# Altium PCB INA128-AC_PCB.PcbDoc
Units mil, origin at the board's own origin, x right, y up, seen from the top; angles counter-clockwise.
Board outline 3000 x 2500 mil, 2 copper layers (Top Layer, Bottom Layer); 43 components, 14 nets, 87 pads, 13 vias.
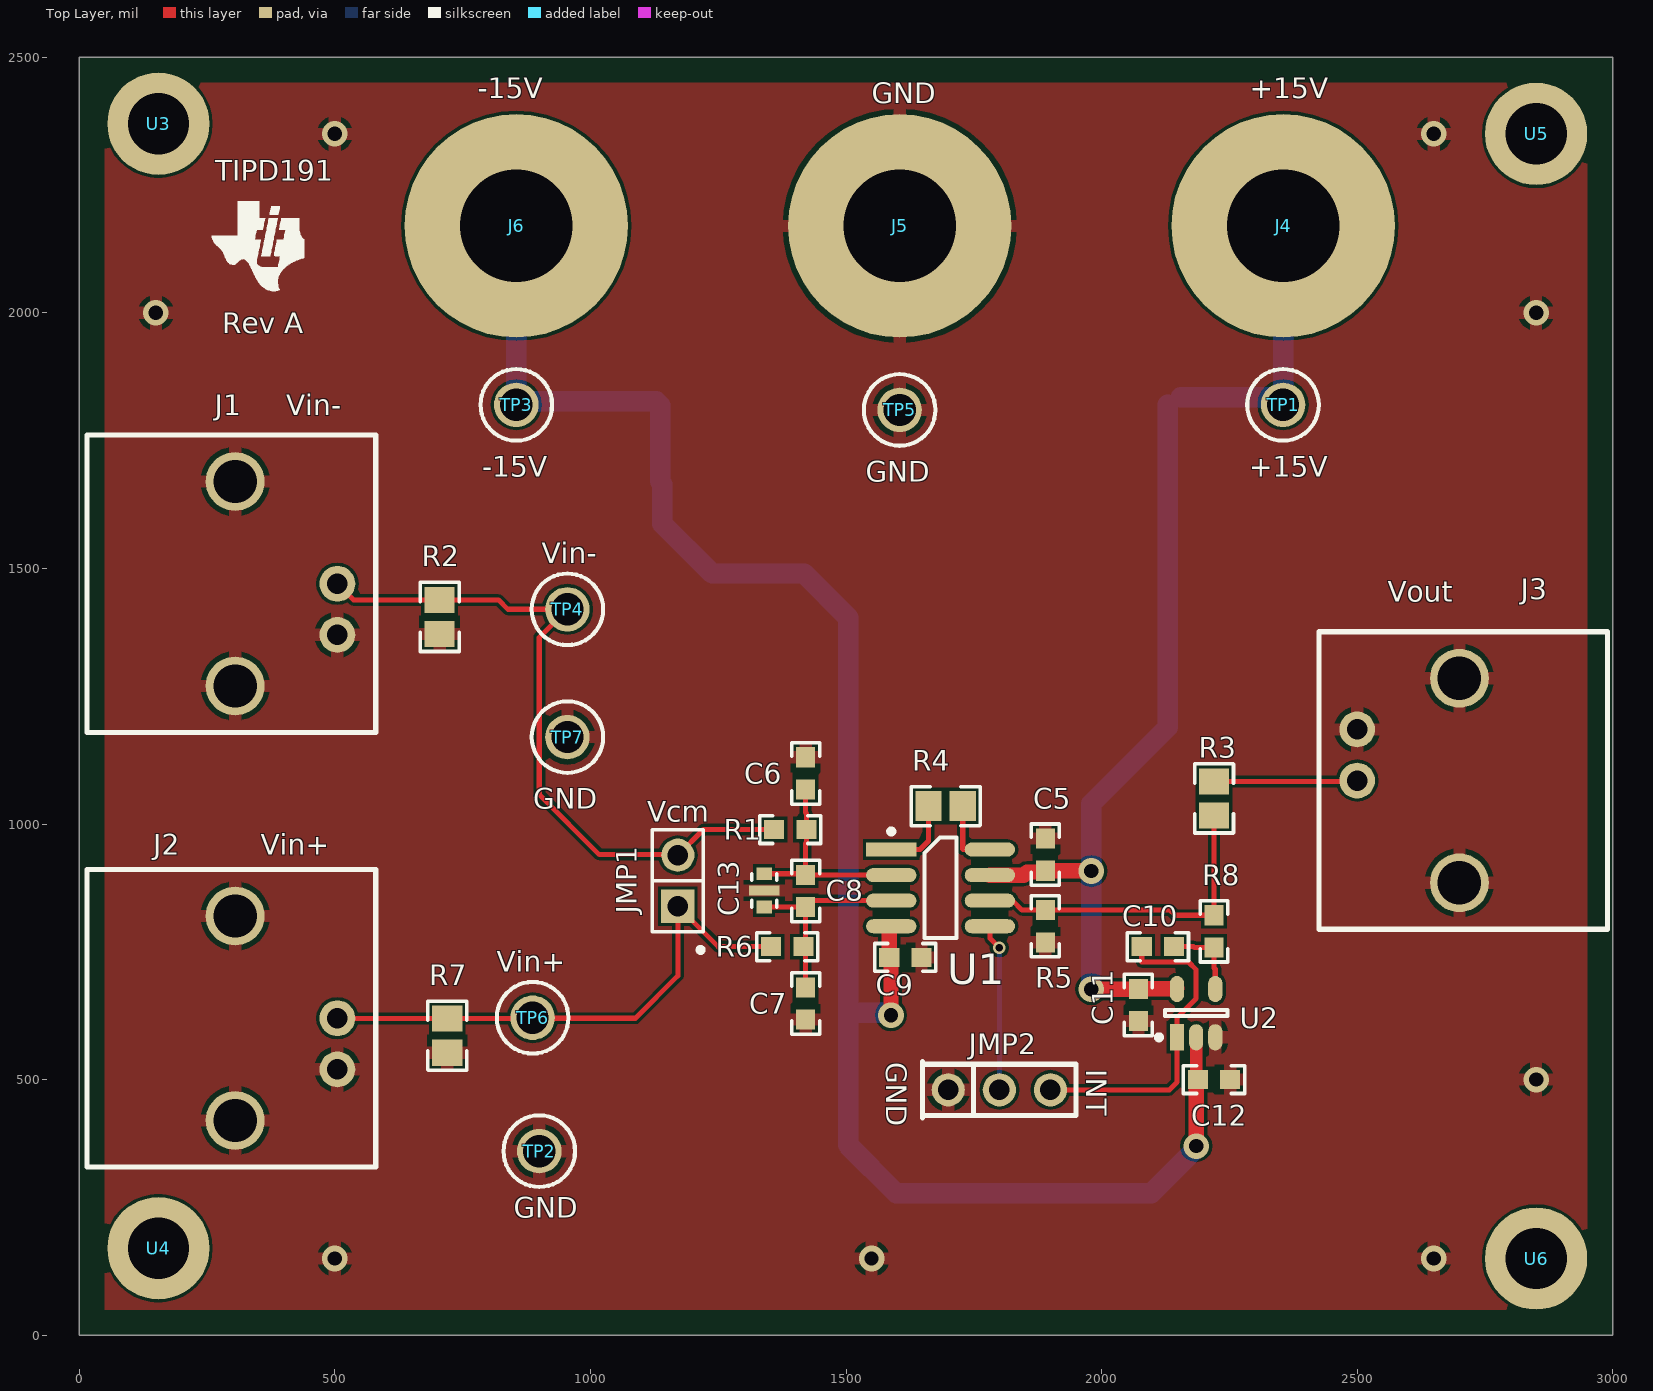
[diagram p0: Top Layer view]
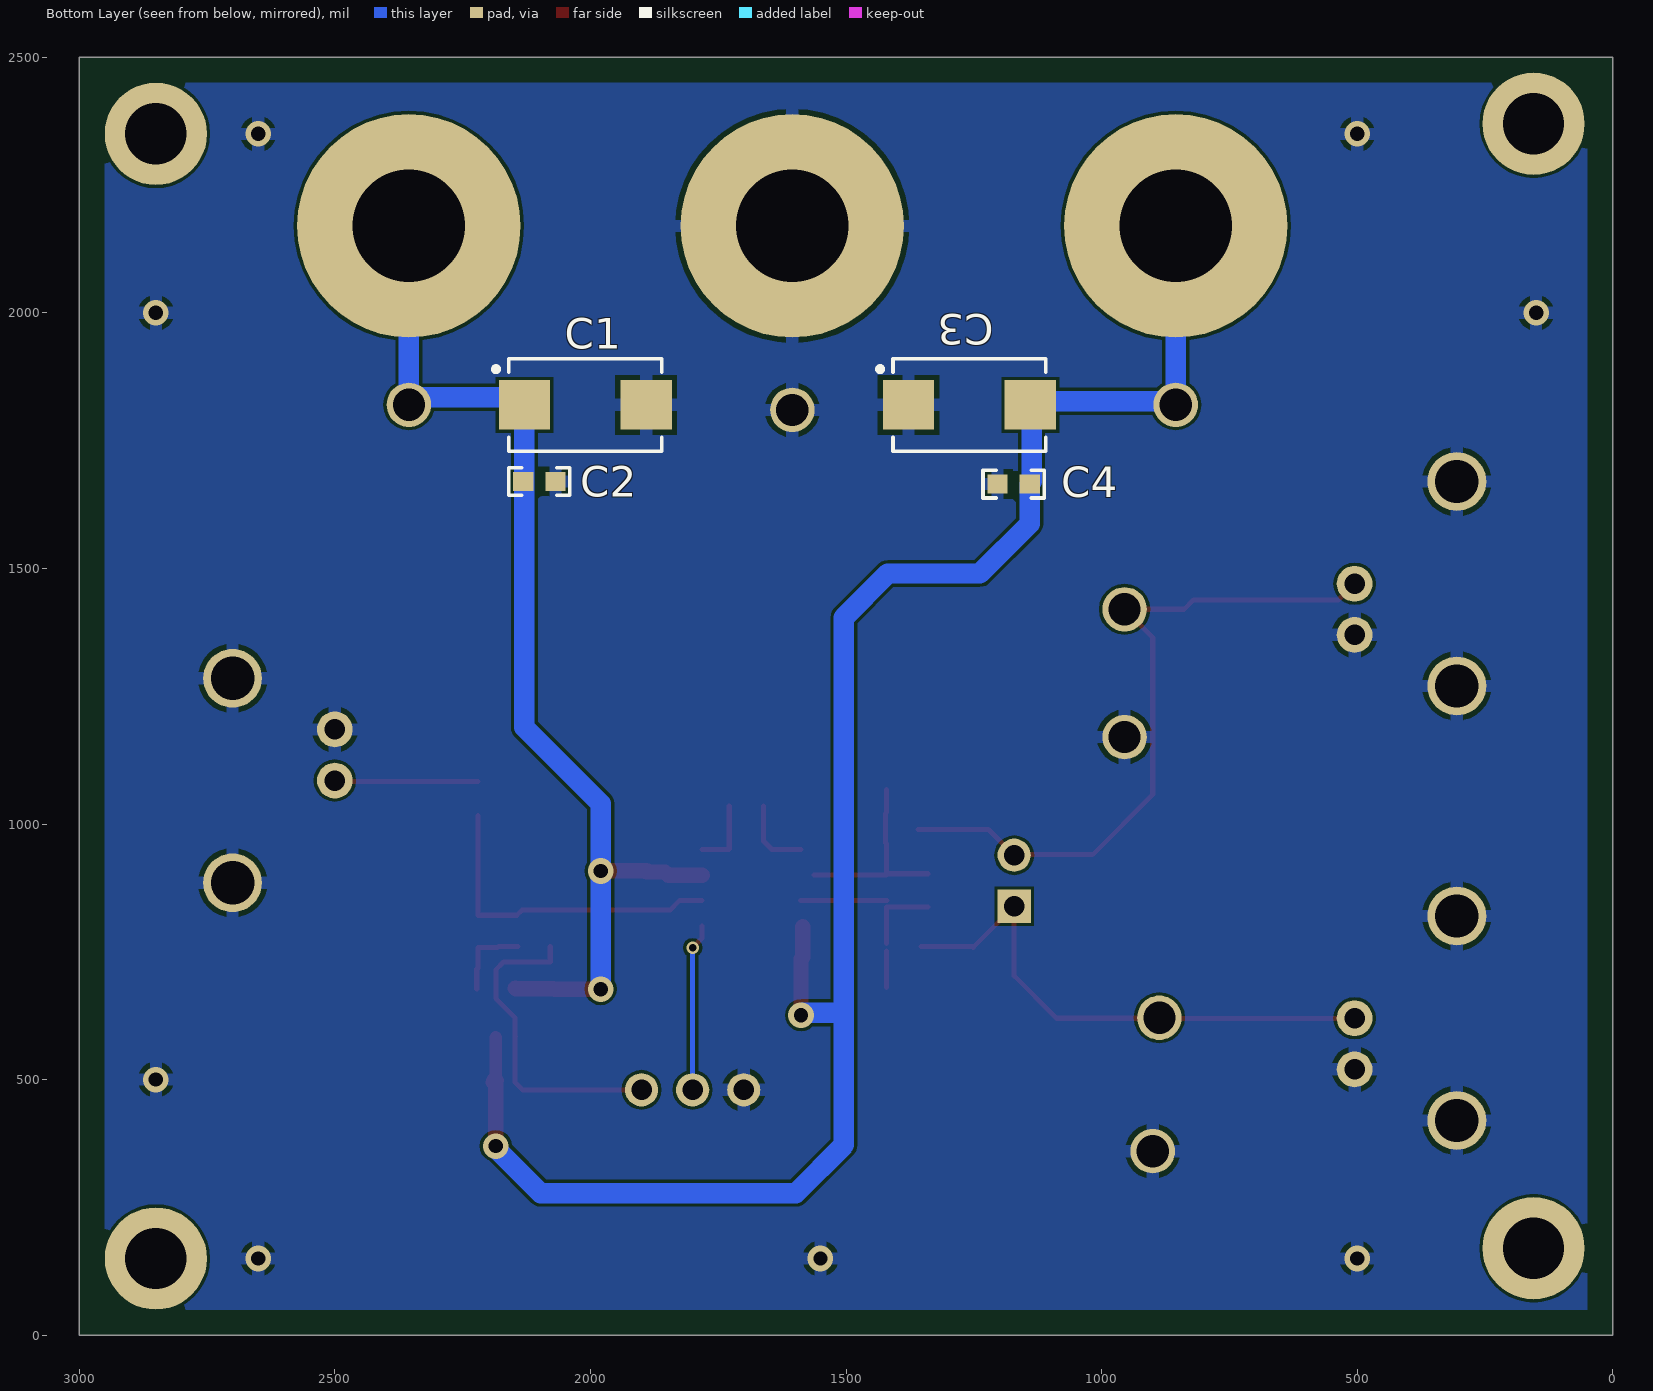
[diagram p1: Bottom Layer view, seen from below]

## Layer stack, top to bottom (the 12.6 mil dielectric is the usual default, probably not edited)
Top Layer: signal copper 1.4
Dielectric: core 12.6, FR-4, Dk 4.8
Bottom Layer: signal copper 1.4

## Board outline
0,2500 0,0 3000,0 3000,2500 0,2500

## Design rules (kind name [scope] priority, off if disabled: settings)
AssemblyTestPointUsage [All] p1 off:
AssemblyTestpoint [All] p1 off: testpointundercomponent=TRUE minsize=40 maxsize=100 preferedsize=60 minholesize=0 maxholesize=40 preferedholesize=32 testpointgrid=1 usegrid=TRUE gridtolerance=0.01 allowsidetop=TRUE allowsidebottom=TRUE
Clearance [All] p1: gap=6
ComponentClearance [All] p1 off: gap=10 collisioncheckmode=3 verticalgap=10 showdistances=FALSE
DiffPairsRouting [All] p1 off: maxlimit=10 minlimit=10 mostfreqgap=10 maxuncoupledlength=500
FabricationTestPointUsage TestPointUsage [All] p1 off: valid=0 allowmultiple=FALSE
FabricationTestpoint Testpoint [All] p1 off: side=3 testpointundercomponent=TRUE minsize=40 maxsize=100 preferedsize=60 minholesize=0 maxholesize=40 preferedholesize=32 testpointgrid=1 allowsidetop=TRUE allowsidebottom=TRUE usegrid=TRUE gridtolerance=0.01
FanoutControl Fanout_BGA [IsBGA] p1 off: bgadir=Out bgaviamode=Centered fanoutstyle=Auto fanoutdirection=Alternating viagrid=1 // Fanout_BGA (Default Rule)
FanoutControl Fanout_LCC [IsLCC] p2 off: bgadir=Out bgaviamode=Centered fanoutstyle=Auto fanoutdirection=Alternating viagrid=1 // Fanout_LCC (Default Rule)
FanoutControl Fanout_SOIC [IsSOIC] p3 off: bgadir=Out bgaviamode=Centered fanoutstyle=Auto fanoutdirection=Alternating viagrid=1 // Fanout_SOIC (Default Rule)
FanoutControl Fanout_Small [(CompPinCount < 5)] p4 off: bgadir=Out bgaviamode=Centered fanoutstyle=Auto fanoutdirection=OutThenIn viagrid=1 // Fanout_Small (Default Rule)
FanoutControl Fanout_Default [All] p5 off: bgadir=Out bgaviamode=Centered fanoutstyle=Auto fanoutdirection=Alternating viagrid=1 // Fanout_Default (Default Rule)
Height [All] p1 off: minheight=0 maxheight=1000 prefheight=500
HoleSize [All] p1: absolutevalues=TRUE maxlimit=400 minlimit=15 maxpercent=80.000 minpercent=20.000
HoleToHoleClearance [All] p1: gap=8 allowstackedmicrovias=TRUE
LayerPairs [All] p1 off: enforce=FALSE
MinimumSolderMaskSliver [All] p1: minsoldermaskwidth=4
PolygonConnect PolygonConnect_1 [InPadClass('GNDVia')] p1: connectstyle=Direct reliefconductorwidth=10 reliefentries=4 polygonreliefangle="90 Angle" airgapwidth=10
PolygonConnect [All] p2: connectstyle=Relief reliefconductorwidth=25 reliefentries=4 polygonreliefangle="90 Angle" airgapwidth=10
RoutingVias [All] p1: holewidth=15 width=25 viastyle="Through Hole" minholewidth=15 minwidth=25 maxholewidth=400 maxwidth=500
SilkToSilkClearance [All] p1: silktosilkclearance=5
SilkscreenOverComponentPads [IsPad] p1: minsilkscreentomaskgap=5
SolderMaskExpansion [All] p1: expansion=2
Width Width_1 [InNetClass('Power')] p1: maxlimit=100 minlimit=10 preferedwidth=30 minimp=50.000000 maximp=50.000000 favimp=50.000000
Width [All] p2: maxlimit=100 minlimit=6 preferedwidth=10
10 further rules are at their usual default settings.

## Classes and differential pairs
net class Power: +15V -15V

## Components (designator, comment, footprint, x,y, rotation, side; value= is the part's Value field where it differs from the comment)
C1 "293D106X9050E2TE3" 7343-43 2010,1820 r180 bottom
C2 "06033D104KAT2A" 0603 2100,1670 r180 bottom
C3 "293D106X9050E2TE3" 7343-43 1258.5,1820 r180 bottom
C4 "06033D104KAT2A" 0603 1172,1665 r180 bottom
C5 "06033D104KAT2A" 0603 1890,940 r90 top
C6 "06031C102JAT2A" 0603 1421,1099 r270 top
C7 "06031C102JAT2A" 0603 1421,649 r270 top
C8 "06031C103JAT2A" 0603 1421,869 r270 top
C9 "06033D104KAT2A" 0603 1616,739 r0 top
C10 "06033D104KAT2A" 0603 2110,760 r180 top
C11 "06033D104KAT2A" 0603 2072,646 r90 top
C12 "06033D104KAT2A" 0603 2220,500 r180 top
C13 "500X14W103MV4T" X2Y_0603 1340,870 r90 top
J1 "Vin-" "Right Angle BNC" 505,1470 r90 top
J2 "Vin+" "Right Angle BNC" 505,620 r90 top
J3 "Vout" "Right Angle BNC" 2500,1085 r270 top
J4 "+15V" "JACK NON-INSULATED .218\"" 2355,2170 r90 top
J5 "GND" "JACK NON-INSULATED .218\"" 1605,2170 r90 top
J6 "-15V" "JACK NON-INSULATED .218\"" 855,2170 r90 top
JMP1 "Vcm" "Header 100mil, 1x2" 1171,889 r90 top
JMP2 "GND" JUMP3 1700,480 r0 top
R1 "CPF0603B100KE" 0603 1391,989 r0 top
R2 "CRCW080549R9FKEA" 0805 705,1405 r90 top
R3 "CRCW080549R9FKEA" 0805 2220,1050 r270 top
R4 "CRCW0805511RFKEA" 0805 1695,1035 r180 top
R5 "CRCW060310K0FKEA" 0603 1890,800 r90 top
R6 "CPF0603B100KE" 0603 1385,760 r0 top
R7 "CRCW080549R9FKEA" 0805 720,586 r90 top
R8 "CRCW06031M00FKEA" 0603 2220,790 r90 top
TIPD191 "SE AC Coupled" TI_Symbol_Overlay_Small 350,2130 r0 top
TP1 "+15V" Keystone5005 2355,1820 r90 top
TP2 "GND" Keystone5006 900,360 r90 top
TP3 "-15V" Keystone5009 855,1820 r90 top
TP4 "Vin-" Keystone5005 955,1420 r90 top
TP5 "GND" Keystone5006 1605,1810 r90 top
TP6 "Vin+" Keystone5005 887,621 r90 top
TP7 "GND" Keystone5006 955,1170 r90 top
U1 "INA118U" "SOIC-8 (D) low density" 1685,875 r0 top
U2 "OPA188AIDBV" "SOT23-5 (DBV) low density" 2185,630 r90 top
U3 "Standoff" MHOLE1 155,2370 r0 top
U4 "Standoff" MHOLE1 155,170 r0 top
U5 "Standoff" MHOLE1 2850,2350 r0 top
U6 "Standoff" MHOLE1 2850,150 r0 top

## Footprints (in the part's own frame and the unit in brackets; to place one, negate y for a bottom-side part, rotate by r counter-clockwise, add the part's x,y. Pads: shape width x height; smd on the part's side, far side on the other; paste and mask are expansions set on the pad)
0603 [mm] "0603 from SM-752 data"
  rect 1x0.95 smd: 1(-0.8,0) 2(0.8,0)
  silkscreen extent -1.52,-0.69 1.52,0.69, body extent -0.87,-0.47 0.87,0.47, height 0.85
0805 [mm] "0805 from SM-752 data"
  rect 1.3x1.5 smd: 1(-0.85,0) 2(0.85,0)
  silkscreen extent -1.72,-0.97 1.72,0.97, body extent -1.1,-0.72 1.1,0.72, height 1.1
7343-43 [mm] "Medium density IPC based on Kemet T495 series"
  rect 2.55x2.45 smd: 1(-3.025,0) 2(3.025,0)
  silkscreen extent -4.56,-2.3 3.8,2.3, body extent -3.8,-2.3 3.8,2.3, height 4.3
"Header 100mil, 1x2" [mm] "Header 100mil, 1x2"
  rect 1.65x1.65 hole 1.016 mask+0: 1(-1.27,0)
  round 1.65 hole 1.016 mask+0: 2(1.27,0)
  silkscreen extent -3.56,-1.27 2.54,1.27, body extent -2.54,-1.27 2.54,1.27, height 8.38
"JACK NON-INSULATED .218\"" [mil] "JACK NON-INSULATED .218\""
  round 437 hole 220: 1(0,0)
JUMP3 [mil]
  round 65 hole 40: 1(0,0) 2(100,0) 3(200,0)
  silkscreen extent -50,-55 250,55
Keystone5005 [mil] "Keystone Compact loops"
  round 87 hole 63: 1(0,0)
  silkscreen extent -70,-70 70,70, body extent -63,-63 62,63, height 225
Keystone5006 [mil] "Keystone Compact loops"
  round 87 hole 63: 1(0,0)
  silkscreen extent -70,-70 70,70, body extent -63,-63 62,63, height 225
Keystone5009 [mil] "Keystone Compact loops"
  round 87 hole 63: 1(0,0)
  silkscreen extent -70,-70 70,70, body extent -63,-63 62,63, height 225
MHOLE1 [mil]
  round 200 hole 120: 0(0,0)
"Right Angle BNC" [mil]
  round 70 hole 40: 1(0,0) 2(-100,0)
  round 115 hole 85: 3(200,200) 4(-200,200)
  silkscreen extent -291,-75 291,490, body extent -290,-50 291,1325, height 519
"SOIC-8 (D) low density" [mm] "SOIC, 8-Leads, Body 4.9x3.9mm, Pitch 1.27mm, IPC Low Density"
  rect 2.5x0.7 smd: 1(-2.45,1.905)
  oval 2.5x0.7 smd: 2(-2.45,0.635) 3(-2.45,-0.635) 4(-2.45,-1.905) 5(2.45,-1.905) 6(2.45,-0.635) 7(2.45,0.635) 8(2.45,1.905)
  silkscreen extent -2.57,-2.5 0.8,2.93, body extent -2,-2.5 2,2.5, height 1.75
"SOT23-5 (DBV) low density" [mm] "SOT23, 5-Leads, Body 2.9x1.6mm, Pitch 0.95mm, Lead Span 2.8mm, IPC Low Density"
  rect 1.3x0.7 smd: 1(-1.2,0.95)
  oval 1.3x0.7 smd: 2(-1.2,0) 3(-1.2,-0.95) 4(1.2,-0.95) 5(1.2,0.95)
  silkscreen extent -1.32,-1.55 0.15,1.97, body extent -0.9,-1.55 0.9,1.55, height 1.19
TI_Symbol_Overlay_Small [mil]
  silkscreen extent -90,-88 91,88
X2Y_0603 [mm]
  rect 0.64x0.76 smd: 1(-0.83,0) 2(0.83,0)
  rect 0.51x1.52 smd: 3(0,0)
  silkscreen extent -0.82,-0.63 0.82,0.63, body extent -0.88,-0.51 0.88,0.51, height 0.75

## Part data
C1 C3: "CAP, TA, 10 µF, 50 V, +/- 10%, 0.8 ohm, SMD"
C2 C4 C5 C9 C10 C11 C12: "CAP, CERM, 0.1 µF, 25 V, +/- 10%, X5R, 0603"
C6 C7: "CAP, CERM, 1000 pF, 100 V, +/- 5%, X7R, 0603"
C8: "CAP, CERM, 0.01 µF, 100 V, +/- 5%, X7R, 0603"
C13: "CAP, CERM, 0.01 µF, 50 V, +/- 20%, X7R, 0603"
J1 J2 J3: library part "BNC Right Angle", "Right Angle BNC Connector"
J4 J5 J6: library part "Banana Jack, Solder", "JACK NON-INSULATED .218\""
JMP1: library part Jumper2
JMP2: library part JUMP3
R1 R6: "RES, 100 k, 0.1%, 0.063 W, 0603"
R2 R3 R7: "RES, 49.9, 1%, 0.125 W, 0805"
R4: "RES, 511, 1%, 0.125 W, 0805"
R5: "RES, 10.0 k, 1%, 0.1 W, 0603"
R8: "RES, 1.00 M, 1%, 0.1 W, 0603"
TIPD191: library part TI_Logo, "Texas Instrument Corporate Signature"
TP1 TP4 TP6: library part 5005, "Test Point, TH, Compact, Red"
TP2 TP5 TP7: library part 5006, "Test Point, TH, Compact, Black"
TP3: library part 5009, "Test Point, TH, Compact, Yellow"
U1: "Precision, Low Power  INSTRUMENTATION AMPLIFIER, SOIC-8"
U2: "Precision, Low-Noise, Rail-to-Rail Output, 36-V, Zero-Drift Operational Amplifier, SOT23-5"
U3 U4 U5 U6: library part "Standoff, 1\", 4-40, Alum, F-F", "STANDOFF HEX 4-40THR ALUM 1\"L"

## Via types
v1: diameter 50, hole 28, Top Layer to Bottom Layer, 12 vias
v2: diameter 25, hole 15, Top Layer to Bottom Layer, 1 vias

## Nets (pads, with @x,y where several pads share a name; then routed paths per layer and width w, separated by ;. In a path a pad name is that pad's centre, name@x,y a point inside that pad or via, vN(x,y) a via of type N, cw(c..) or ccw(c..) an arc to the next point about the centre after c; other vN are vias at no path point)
+15V: C1.1 C2.1 C5.1 C11.2 J4.1 TP1.1 U1.7 U2.5 | length 2101.7
  Top Layer w30: U1.7 1848,900 1854,906 C5.1@1891,906 ; C5.1 v1@1978.5,908.5 ; v1(1980,677) C11.2@2070,677 ; C11.2 2145.5,677.5 U2.5@2147,679
  Bottom Layer w40: v1(1980,677) 1980,901 v1@1982,903 ; v1(1980,908) 1980,1040 2129.09,1189.09 C1.1 ; C1.1@2155,1835 2355,1835 J4.1
-15V: C3.2 C4.2 C9.1 C12.2 J6.1 TP3.1 U1.4 U2.2 | length 3561.2
  Top Layer w25: C12.2@2185,499 U2.2
  Top Layer w30: C9.1 U1.4@1584.5,799.5 ; C9.1@1585,740 1588,737 v1(1588,626) ; C12.2@2184,498 C12.2@2185,499 ; v1(2185,370) 2185,495 C12.2@2188,498 ; C12.2@2188.5,496.5 C12.2@2190,495 ; C12.2@2188.5,498 C12.2
  Bottom Layer w40: J6.1 855,1827 1129,1827 1137,1819 1137,1670 C4.2@1140,1667 ; C4.2 1140.5,1587.5 1238,1490 1418,1490 1504,1404 1504,631 ; v1@1584,631 1504,631 ; v1@2185,366 2097,278 1598,278 1504,372 1504,631
GND: C1.2 C2.2 C3.1 C4.1 C5.2 C6.1 C7.2 C9.2 C11.1 C12.1 C13.3 J1.2 J1.3 J1.4 J2.2 J2.3 J2.4 J3.2 J3.3 J3.4 J5.1 JMP2.1 R2.1 R5.1 R7.1 TP2.1 TP5.1 TP7.1 U2.3
  other v1: 500,150 1550,150 2650,150 2850,500 150,2000 2850,2000 500,2350 2650,2350
NetC6_2: C6.2 C8.1 C13.2 R1.2 U1.2 | length 387.1
  Top Layer w10: C13.2 C8.1@1417.32,902.68 ; C6.2 1421,1022.31 1422.5,1020.82 R1.2 1422.5,963.1 1421,961.6 C8.1 U1.2@1562.5,900.5
NetC7_1: C7.1 C8.2 C13.1 R6.2 U1.3 | length 387.9
  Top Layer w10: C13.1 C8.2@1417.32,837.32 ; C8.2@1420,850 U1.3 ; C7.1 R6.2@1421,751 ; R6.2@1421,766 C8.2
NetC10_1: C10.1 R8.1 U2.4 | length 161.4
  Top Layer w10: C10.1 2180,760 2181.5,758.5 R8.1 2220,718.4 2222.4,716 U2.4
NetC10_2: C10.2 JMP2.3 U2.1 | length 632.6
  Top Layer w10: JMP2.3 2132.6,480 2147.6,495 U2.1 U2.1@2147.6,583.4 ; C10.2 2078.5,730.5 2079,730 2170,730 2185,715 2185,658.4 2147.6,621 U2.1@2147.6,583.4 ; U2.1@2147,584 U2.1@2147.6,583.4
NetJ1_1: J1.1 JMP1.2 R1.1 R2.2 TP4.1 | length 1378.9
  Top Layer w10: J1.1 536.54,1438.46 R2.2 820,1438.46 838.46,1420 TP4.1 900,1365 900,1057.5 1017.5,940 JMP1.2@1165,940 ; JMP1.2 1221,989 R1.1
NetJ2_1: J2.1 JMP1.1 R6.1 R7.2 TP6.1 | length 1043
  Top Layer w10: J2.1@513.46,619.46 R7.2 TP6.1@885.46,619.46 ; TP6.1@887,620 1088,620 1171,703 JMP1.1 1250,760 ; 1251,759 1250,760 ; R6.1 1250,760
NetJ3_1: J3.1 R3.1 | length 278.5
  Top Layer w10: R3.1 J3.1@2498.54,1083.46
NetJMP2_2: JMP2.2 U1.5 | length 327.7
  Top Layer w10: U1.5 1781.46,776.54 v2(1800,758)
  Bottom Layer w10: JMP2.2 v2(1800,758)
NetR3_2: R3.2 R5.2 R8.2 U1.6 | length 645.4
  Top Layer w10: U1.6 1826,850 1844.5,831.5 R5.2 2133.87,831.5 2143.87,821.5 R8.2 R3.2
NetR4_1: R4.1 U1.8 | length 137.4
  Top Layer w10: R4.1 1728.46,951 1729.46,950 U1.8
NetR4_2: R4.2 U1.1 | length 148.3
  Top Layer w10: U1.1 1645,950 1661.54,966.54 R4.2
pads on no net: U3.0 U4.0 U5.0 U6.0

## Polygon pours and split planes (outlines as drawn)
GND on Top Layer "Top Layer-No Net" (solid, remove dead copper, pour order 12): 50,2450 50,50 2950,50 2950,2450 50,2450
GND on Bottom Layer "Bottom Layer-No Net" (solid, remove dead copper, pour order 14): 50,2450 50,50 2950,50 2950,2450 50,2450

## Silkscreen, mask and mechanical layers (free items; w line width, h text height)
Top Overlay:
  text "Rev A" at 280,1960 h40
  text "INT" at 1970,520 h40 r270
